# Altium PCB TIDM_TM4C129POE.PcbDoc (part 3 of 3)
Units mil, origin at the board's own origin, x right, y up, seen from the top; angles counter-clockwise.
Board outline 4950 x 3450 mil, 4 copper layers (Component Side, Ground Plane, Power Plane, Solder Side), stack 59.6 mil thick; 159 components, 154 nets, 570 pads, 297 vias.
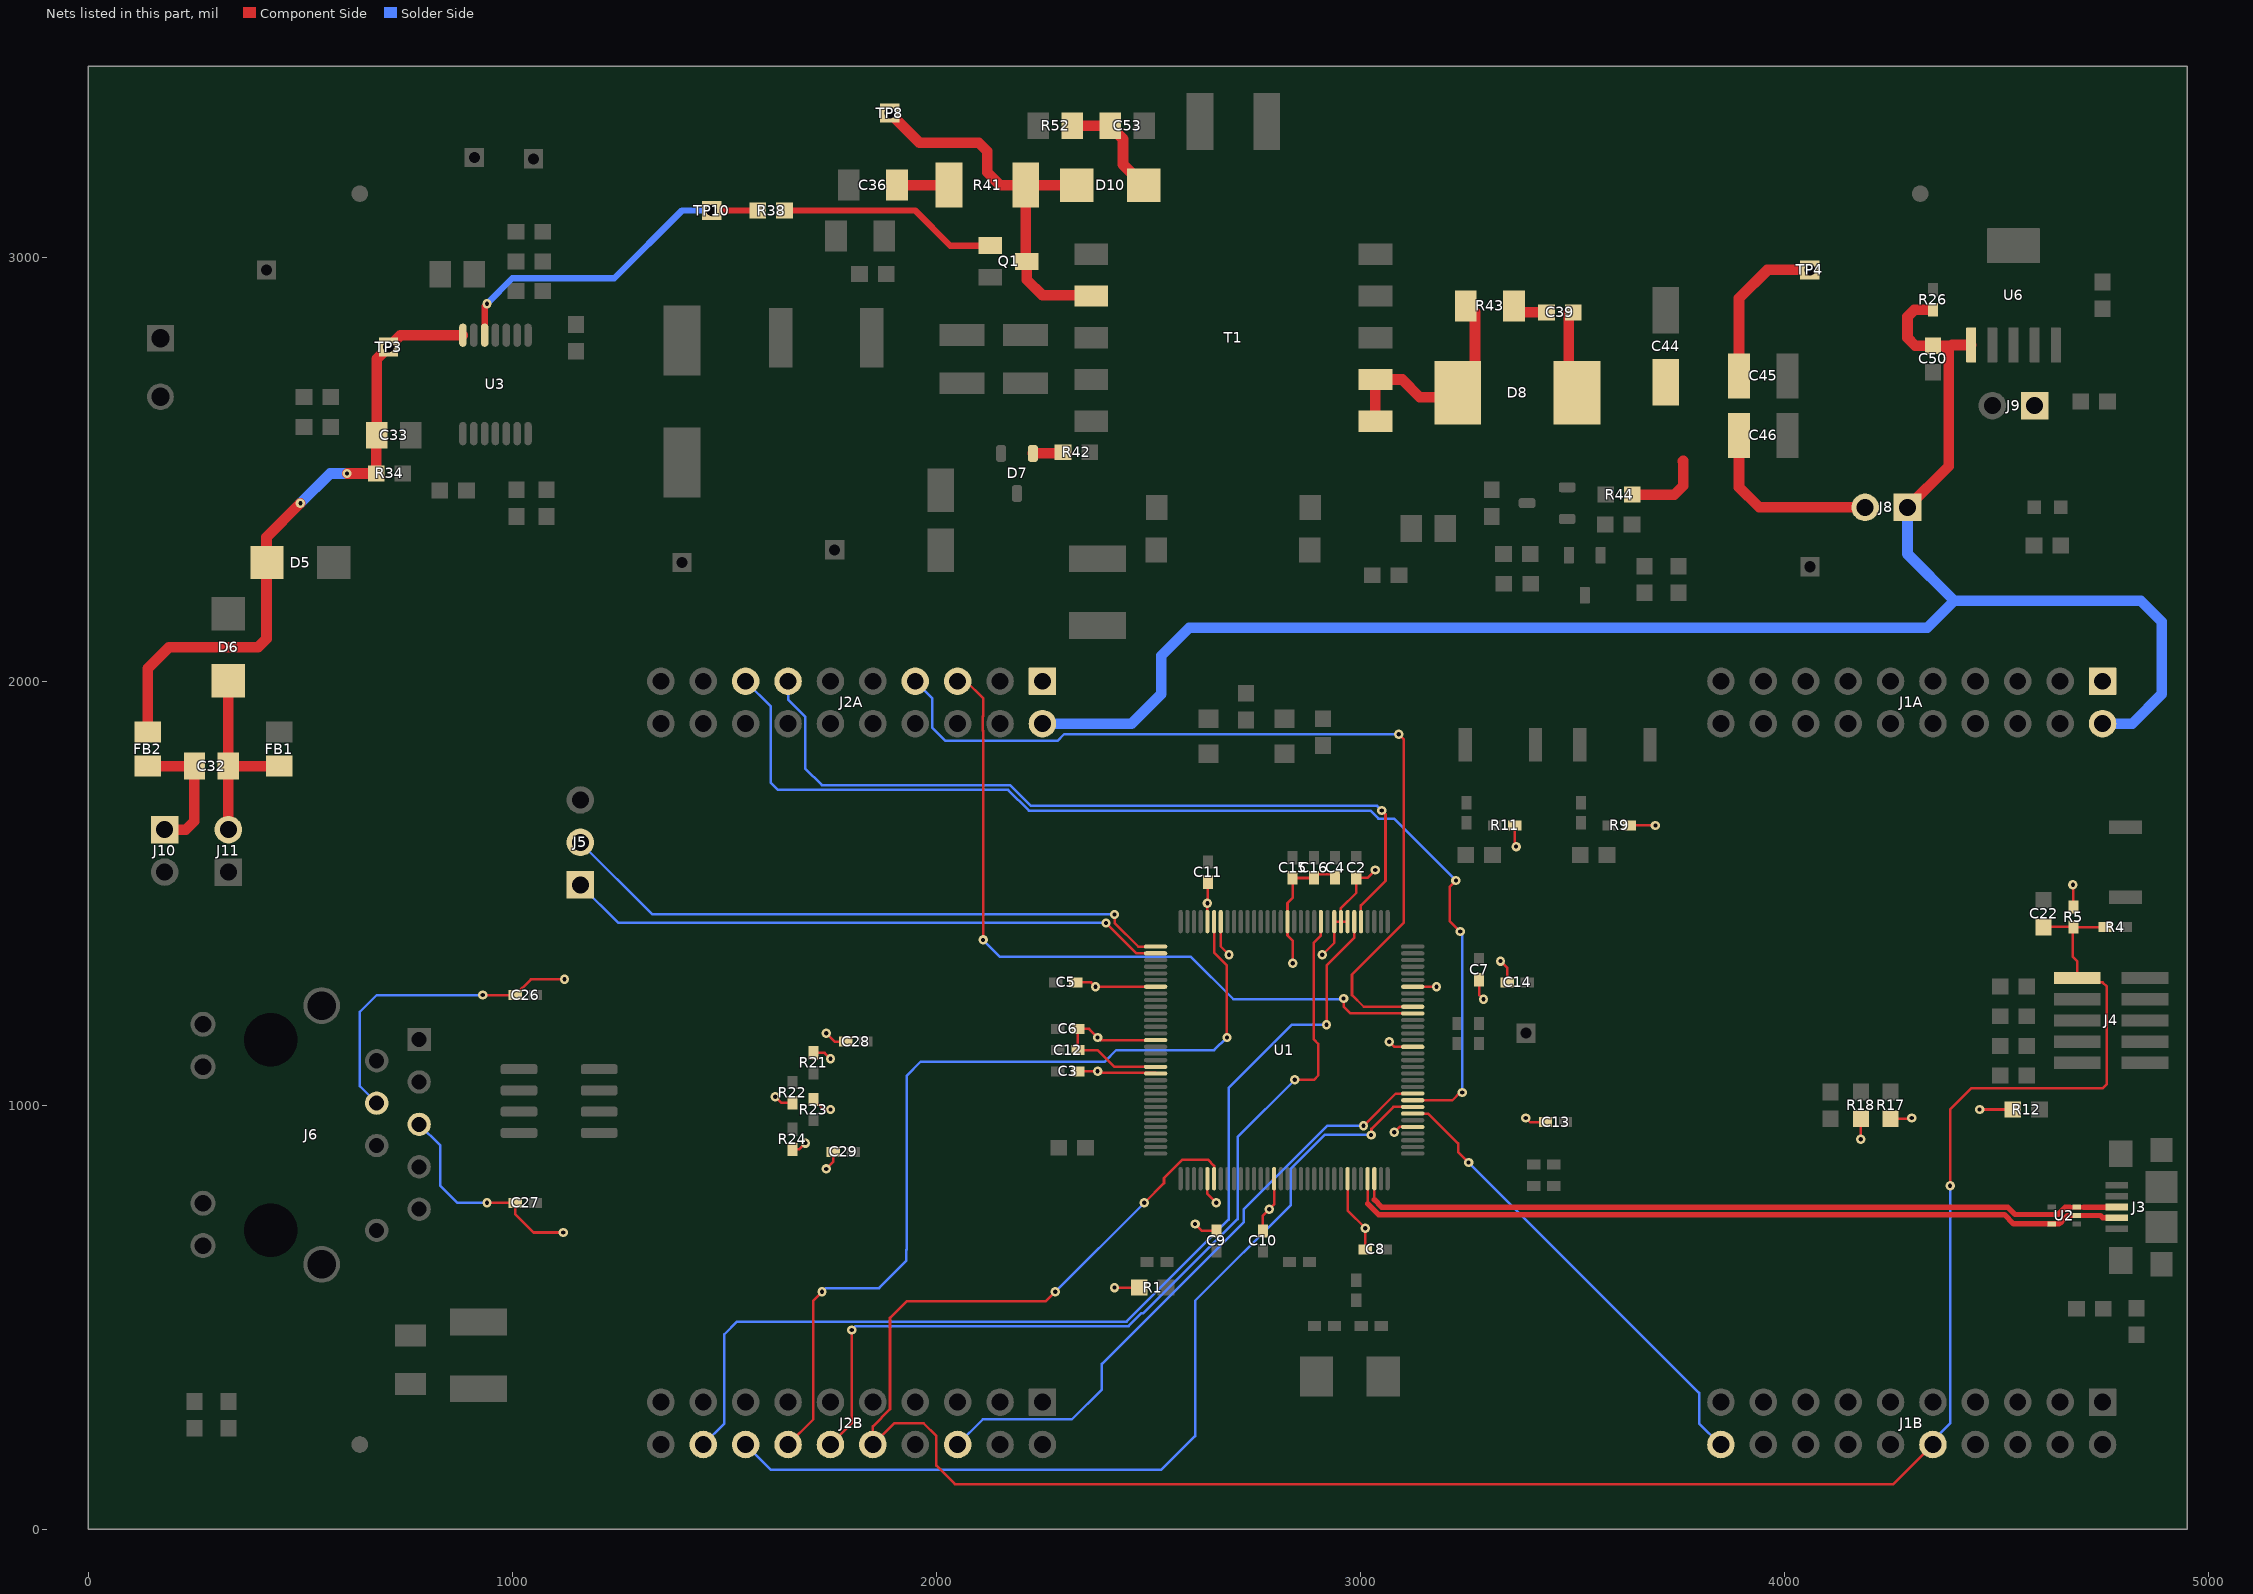
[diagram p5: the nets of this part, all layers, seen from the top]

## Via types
v1: diameter 22, hole 10, Component Side to Solder Side, 297 vias

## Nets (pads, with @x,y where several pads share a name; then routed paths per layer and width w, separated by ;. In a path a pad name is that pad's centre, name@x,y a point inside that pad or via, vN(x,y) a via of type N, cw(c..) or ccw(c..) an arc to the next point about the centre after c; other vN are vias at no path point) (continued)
POE_NET08: D10.2 Q1.3 R41.2 T1.4 TP8.1 | length 933
  Component Side w25: TP8.1@1890,3340 1960,3270 2100,3270 2120,3250 2120,3200 2150,3170 R41.2@2210.55,3170 ; D10.2@2331.26,3170 R41.2@2210.55,3170 ; T1.4@2365,2908.43 2363.43,2910 2250,2910 2213.31,2946.69 Q1.3@2213.31,2990 2210.55,2992.76 R41.2@2210.55,3170
POE_NET09: D7.1 R42.1 | length 72.2
  Component Side w25: D7.1@2227.4,2537.24 2295.75,2537.24 R42.1@2298.5,2540
POE_NET10: C36.1 R41.1 | length 122.4
  Component Side w25: C36.1@1907.09,3170 R41.1@2029.45,3170
POE_NET11: D8.2 R43.1 T1.9 T1.10 | length 526.7
  Component Side w25: T1.10@3035,2613.15 T1.9@3035,2711.57 3098.43,2711.57 3140,2670 3229.19,2670 3270,2710.81 R43.1@3270,2870
POE_NET12: C39.1 C44.1 C45.1 C46.1 D8.1 J8.2 R44.2 TP4.1 | length 1205
  Component Side w25: C39.1@3491.5,2870 3491.5,2699 D8.1@3510.49,2680 ; R44.2@3641.18,2440 3740,2440 3761.18,2461.18 3761.18,2520 3759.68,2518.5 ; C46.1@3892.6,2580 3892.6,2457.4 3940,2410 J8.2@4190,2410 ; C45.1@3892.6,2720 3892.6,2902.91 3959.68,2970 TP4.1@4059.68,2970
POE_NET13: C39.2 R43.2 | length 78.5
  Component Side w25: R43.2@3350,2870 C39.2@3428.5,2870
POE_NET14: C53.2 D10.1 R52.1 | length 262.6
  Component Side w25: R52.1@2320,3310 C53.2@2410,3310 2410,3308.75 2440,3278.75 2440,3218.74 D10.1@2488.74,3170
POE_NET15: C33.2 D5.2 FB2.2 R34.1 TP3.1 U3.7 | length 1516
  Component Side w25: FB2.2@140,1880 140,2030 190,2080 400,2080 420,2100 420,2340 v1(500,2420) ; v1(610,2490) R34.1@678.5,2490 678.5,2578.5 C33.2@680,2580 680,2760 TP3.1@708.07,2788.07 736.14,2816.14 U3.7@882.46,2816.14
  Solder Side w25: v1(500,2420) 570,2490 v1(610,2490)
POE_VN: C32.2 FB2.1 J10.1 | length 318.3
  Component Side w25: FB2.1@140,1800 C32.2@250,1800 250,1670 230,1650 J10.1@180,1650
POE_VP: C32.1 D6.1 FB1.1 J11.2 | length 471.3
  Component Side w25: J11.2@330,1650 C32.1@330,1800 ; D6.1@330,2001.26 C32.1@330,1800 ; FB1.1@450,1800 C32.1@330,1800
PP0: J2A.5 U1.118 | length 1746.1
  Component Side w6: J2A.5@2050,2000 2070,2000 2110,1960 2110,1917.73 2109.52,1917.25 2109.52,1883.23 2110,1882.75 v1(2110,1390) ; v1(2960.22,1252) 2960.22,1233.22 2960,1233 2976.39,1216.61 U1.118@3123.15,1216.61
  Solder Side w6: v1(2110,1390) 2150,1350 2600,1350 2700,1250 2960,1250 2960.22,1250.22 v1(2960.22,1252)
PP1: J2A.7 U1.119 | length 2070.8
  Component Side w6: v1(3090,1875) 3102.44,1862.56 3102.44,1430.59 2980,1308.14 2980,1260 3007.64,1232.36 U1.119@3123.15,1232.36
  Solder Side w6: J2A.7@1950,2000 1990,1960 1990,1917.73 1990.48,1917.25 1990.48,1890 2020.96,1859.52 2285.79,1859.52 2301.27,1875 v1(3090,1875)
PP2: J1B.20 U1.103 | length 1103.8
  Component Side w6: U1.103@3123.15,980.39 3159.44,980.39 3187.68,952.15 3187.87,952.15 3230.1,909.92 3230.1,889.9 v1(3255,865)
  Solder Side w6: v1(3255,865) 3798.42,321.58 3798.42,250 3848.42,200 J1B.20@3850,200
PP3: J2B.16 U1.104 | length 2198
  Component Side w6: v1(3025,930) 3026,930 3026,944.5 3077.64,996.14 U1.104@3123.15,996.14
  Solder Side w6: J2B.16@1550,200 1610,140 2530,140 2610,220 2610,539 2835,764 2835,849.44 2915.56,930 v1(3025,930)
PP4: J2A.15 U1.105 | length 2623.1
  Component Side w6: U1.105@3123.15,1011.89 3216.89,1011.89 3235,1030 v1(3240,1030) ; v1(3225,1530) 3210,1515 3210,1435 v1(3235,1410)
  Solder Side w6: J2A.15@1550,2000 1609.52,1940.48 1609.52,1760.48 1626,1744 2169,1744 2218,1695 3023.13,1695 3042.13,1676 3079,1676 v1(3225,1530) ; v1(3235,1410) 3240,1405 v1(3240,1030) v1@3240,1025
PP5: J2B.6 U1.106 | length 1468.7
  Component Side w6: v1(3007,951.5) 3083.14,1027.64 U1.106@3123.15,1027.64
  Solder Side w6: J2B.6@2050,200 2109.52,259.52 2319.52,259.52 2390,330 2390,390 2725,725 2725,755 2921.5,951.5 v1(3007,951.5)
PQ0: J2A.13 U1.5 | length 1912.5
  Component Side w6: U1.5@3001.1,1433.15 3001.1,1471.1 3059,1529 3059,1686 v1(3050,1695)
  Solder Side w6: J2A.13@1650,2000 1650,1957.25 1690.48,1916.77 1690.48,1794.52 1730,1755 2173.56,1755 2222.56,1706 3039,1706 v1(3050,1695)
PQ1: J2B.18 U1.6 | length 2454.8
  Component Side w6: v1(2920,1190) 2920,1330 2985.35,1395.35 U1.6@2985.35,1433.15
  Solder Side w6: J2B.18@1450,200 1500,250 1500,460 1530,490 2448.35,490 2689,730.65 2689,1040.44 2838.56,1190 v1(2920,1190)
PQ2: J2B.12 U1.11 | length 2126.9
  Component Side w6: J2B.12@1750,200 1800,250 v1(1800,470) ; v1(2845,1060) 2890,1060 2900.36,1070.36 2900.36,1145 2890,1155.36 2890,1383.8 2906.61,1400.42 U1.11@2906.61,1433.15
  Solder Side w6: v1(1800,470) 1809,479 2452.9,479 2483.9,510 2488.19,510 2710,731.81 2710,925 v1(2845,1060)
PQ3: J2B.14 U1.27 | length 2137.5
  Component Side w6: J2B.14@1650,200 1709.52,259.52 1709.52,539.52 v1(1730,560) ; U1.27@2654.65,1433.15 2654.65,1360 2685,1329.65 v1(2685,1160)
  Solder Side w6: v1(1730,560) 1739,569 1864.56,569 1929,633.44 1929,659 1930,660 1930,1070 1963,1103 2397,1103 2424,1130 2655,1130 v1(2685,1160)
RST_N: C22.1 J1B.10 J2B.10 J4.10 R4.1 R5.1 U1.70 | length 5722.5
  Component Side w6: v1(2280,560) 2258,538 1930,538 1890.48,498.48 1890.48,283.23 1850,242.75 J2B.10@1850,200 1900,250 1970,250 2000,220 2000,150 2043.5,106.5 4256.5,106.5 J1B.10@4350,200 ; v1(2490,770) 2536.56,816.56 2536.56,828.44 2580.08,871.97 2640,871.97 2654.65,857.32 U1.70@2654.65,826.85 ; v1(4390.48,810) 4390.48,990.48 4440,1040 4750,1040 4760,1050 4760,1280 4750,1290 J4.10@4681,1290 ; C22.1@4611,1420.5 4681,1420.5 R5.1@4681,1420.38 R5.1@4681,1420 ; J4.10@4689.88,1300 4689.88,1340.12 4680,1350 4680,1419 R5.1@4681,1420 ; R4.1@4756.38,1420 R5.1@4681,1420
  Solder Side w6: v1(2280,560) v1(2490,770) ; J1B.10@4350,200 4350,209.52 4390.48,250 v1(4390.48,810)
TRC_001: Q1.1 R38.2 | length 519.4
  Component Side w15: R38.2@1641.5,3110 1950,3110 2032.6,3027.4 Q1.1@2126.69,3027.4
TRC_002: R38.1 TP10.1 U3.5 | length 805.8
  Component Side w15: U3.5@934.41,2816.14 934.41,2884.41 v1(940,2890) ; TP10.1@1470,3110 R38.1@1578.5,3110
  Solder Side w15: v1(940,2890) 1000,2950 1240,2950 1400,3110 TP10.1@1470,3110
UART0RX: J5.2 U1.33 | length 1470.4
  Component Side w6: v1(2420,1450) 2420,1430 2475.91,1374.09 U1.33@2516.85,1374.09
  Solder Side w6: J5.2@1160,1620 1330,1450 v1(2420,1450)
UART0TX: J5.1 U1.34 | length 1423.8
  Component Side w6: v1(2400,1430) 2471.65,1358.35 U1.34@2516.85,1358.35
  Solder Side w6: J5.1@1160,1520 1250,1430 v1(2400,1430)
USBD_N: J3.2 U1.93 U2.2 U2.5 | length 1855.9
  Component Side w6: 3016.85,767.98 U1.93@3016.85,826.85
  Component Side w12.8: 3016.85,767.98 3042.63,742.2 4518.55,742.2 4540.44,720.31 U2.5@4630.47,720.31 4646.71,720.31 4650.98,724.58 4652.41,724.58 4667.83,740 U2.2@4689.53,740 4745.1,740 4750.69,734.41 J3.2@4783.66,734.41
USBD_P: J3.3 U1.94 U2.3 | length 1822.3
  Component Side w6: 3032.6,777.4 U1.94@3032.6,826.85
  Component Side w10.63: 4673.29,759.68 U2.3@4689.53,759.68 4705.77,759.68
  Component Side w12.8: 3032.6,777.4 3050,760 4525.93,760 4543.55,742.38 4645.04,742.38 4662.34,759.68 4673.29,759.68 ; 4705.77,759.68 4750.37,759.68 4750.69,760 J3.3@4783.66,760
VCC_3P3: C2.1 C3.1 C4.1 C5.1 C6.1 C7.1 C8.1 C9.1 C10.1 C11.1 C12.1 C13.1 C14.1 C15.1 C16.1 C26.1 C27.1 C28.1 C29.1 J1A.1 J2A.1 J6.4 J6.5 J9.1 R1.1 R5.2 R9.2 R11.2 R12.1 R17.2 R18.2 R21.2 R22.2 R23.2 R24.2 U1.7 U1.8 U1.9 U1.16 U1.26 U1.28 U1.39 U1.47 U1.51 U1.52 U1.69 U1.79 U1.90 U1.101 U1.113 U1.122 | length 4344.2
  Component Side w6: v1(930,1260) C26.1@1006.38,1260 1043.37,1296.99 v1(1123,1296.99) ; v1(940,770) C27.1@1006.38,770 1006.38,743.62 1050,700 v1(1120,700) ; v1(1620,1020) 1633.62,1006.38 R22.2@1660,1006.38 ; R24.2@1660,896.38 1676.84,896.38 v1(1691.21,910.75) ; R23.2@1710,1013.62 1733.62,990 v1(1750,990) ; R21.2@1710,1123.62 1736.38,1123.62 v1(1750,1110) ; v1(1740,850) 1756.38,866.38 C29.1@1756.38,890 ; v1(1740,1170) 1760,1150 C28.1@1786.38,1150 ; C5.1@2328.62,1290 2364.61,1290 v1(2375,1279.61) U1.39@2516.85,1279.61 ; C3.1@2333.62,1080 v1(2380,1080) 2383.82,1076.18 2516.85,1076.18 U1.52@2516.85,1074.88 ; v1(2420,570) R1.1@2478.5,570 ; U1.51@2516.85,1090.63 2419.37,1090.63 2380,1130 C12.1@2333.62,1130 C6.1@2333.62,1180 2360,1180 v1(2380,1160) 2386.38,1153.62 U1.47@2516.85,1153.62 ; v1(2610,720) 2626.38,703.62 C9.1@2660,703.62 C9.1@2660,703 ; U1.69@2638.9,826.85 2638.9,791.1 v1(2660,770) ; U1.28@2638.9,1433.15 v1@2638.9,1475.9 ; v1(2638.9,1476.71) v1@2638.9,1475.9 ; C11.1@2640,1526.38 2640,1477 v1@2638.9,1475.9 ; U1.26@2670.39,1433.15 2670.39,1374.61 v1(2690,1355) ; C10.1@2770,703.62 2770,740 v1(2785,755) 2796.38,766.38 U1.79@2796.38,826.85 U1.79@2793.55,824.02 ; v1(2840,1335) 2840,1388.29 2827.87,1400.42 U1.16@2827.87,1433.15 2827.87,1477 2828,1477 2840,1489 C15.1@2840,1536 ; C15.1@2840,1536.38 C15.1@2840,1536 ; v1(2910,1355) 2938.11,1383.11 U1.9@2938.11,1433.15 U1.8@2953.86,1433.15 ; C4.1@2940,1536.38 2940,1544.78 2890,1544.78 C16.1@2890,1536.38 2890,1536 C15.1@2840,1536 ; U1.90@2969.61,826.85 2969.61,751.77 v1(3011.38,710) C8.1@3011.38,660 ; U1.7@2969.61,1433.15 U1.8@2953.86,1433.15 ; v1(3035,1555) 3016.38,1536.38 C2.1@2990,1536.38 2990,1500.86 2953.86,1464.72 U1.8@2953.86,1433.15 ; v1(3068.03,1150) 3080.16,1137.87 U1.113@3123.15,1137.87 ; v1(3079.59,936.4) 3092.09,948.9 U1.101@3123.15,948.9 ; U1.122@3123.15,1279.61 v1(3179.21,1279.61) ; C7.1@3280,1296.38 3280,1260 v1(3290,1250) ; v1(3330,1340) 3346.38,1323.62 C14.1@3346.38,1290 ; R11.2@3363.62,1660 3363.62,1613.38 v1(3367,1610) ; v1(3390,970) 3400,960 C13.1@3436.38,960 ; R9.2@3633.62,1660 v1(3695.5,1660) ; v1(4180,920) R18.2@4180,968.5 R18.2@4180,969 ; R17.2@4250,968.5 4298.5,968.5 v1(4300,970) ; v1(4460,990) R12.1@4538.5,990 ; v1(4680,1520) 4681,1519 R5.2@4681,1467.62 R5.2@4681,1461
  Solder Side w6: J6.4@680,1005 640,1045 640,1220 680,1260 v1(930,1260) ; J6.5@780,955 830,905 830,810 870,770 v1(940,770)
VCC_5P0: C50.1 J1A.2 J2A.2 J8.1 R26.1 U6.1 | length 4140.2
  Component Side w25: J8.1@4290,2410 4387,2507 4387,2778.5 4374,2791.5 ; R26.1@4350,2876.38 4306.38,2876.38 4290,2860 4290,2810 4308.5,2791.5 C50.1@4350,2791.5 4374,2791.5 ; U6.1@4440,2792.87 4395.38,2792.87 4394,2791.5 4374,2791.5
  Solder Side w25: J2A.2@2250,1900 2460,1900 2530,1970 2530,2060 2596.5,2126.5 4336.5,2126.5 4400,2190 ; J8.1@4290,2410 4290,2300 4400,2190 ; J1A.2@4750,1900 4820,1900 4890,1970 4890,2140 4840,2190 4400,2190
pads on no net: D7.2 FID1.1 FID2.1 FID3.1 J3.1 J3.4 J4.7 J6.MH1 J6.MH2 T1.5 T1.6 U1.65 U1.67 U1.72 U1.76 U1.77 U1.102 U2.1

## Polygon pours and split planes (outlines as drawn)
GNDX on Ground Plane (split plane): 2649.92,2250.08 1030,2250.08 1024.39,2249.76 1018.86,2248.82 1013.46,2247.27 1008.27,2245.12 1003.36,2242.4 998.78,2239.15 994.59,2235.41 990.85,2231.22 987.6,2226.64 984.88,2221.73 982.73,2216.54 981.18,2211.14 980.24,2205.61 979.92,2200 979.92,1865.08 50.08,1865.08 50.08,3399.92 2649.92,3399.92
E_SHIELD on Ground Plane (split plane): 987.6,1813.36 990.85,1808.78 994.59,1804.59 998.78,1800.85 1003.36,1797.6 1004.92,1796.73 1004.92,1170 1005.23,1166.08 1006.15,1162.25 1007.66,1158.62 1009.71,1155.26 1012.27,1152.27 1015.26,1149.71 1018.62,1147.66 1022.25,1146.15 1026.08,1145.23 1030,1144.92 1304.92,1144.92 1304.92,875.08 1030,875.08 1026.08,874.77 1022.25,873.85 1018.62,872.34 1015.26,870.29 1012.27,867.73 1009.71,864.74 1007.66,861.38 1006.15,857.75 1005.23,853.92 1004.92,850 1004.92,435.08 50.08,435.08 50.08,1814.92 986.73,1814.92
GND on Ground Plane (split plane): 4899.92,50.08 50.08,50.08 50.08,384.92 1030,384.92 1033.92,385.23 1037.75,386.15 1041.38,387.66 1044.74,389.71 1047.73,392.27 1050.29,395.26 1052.34,398.62 1053.85,402.25 1054.77,406.08 1055.08,410 1055.08,824.92 1330,824.92 1333.92,825.23 1337.75,826.15 1341.38,827.66 1344.74,829.71 1347.73,832.27 1350.29,835.26 1352.34,838.62 1353.85,842.25 1354.77,846.08 1355.08,850 1355.08,1170 1354.77,1173.92 1353.85,1177.75 1352.34,1181.38 1350.29,1184.74 1347.73,1187.73 1344.74,1190.29 1341.38,1192.34 1337.75,1193.85 1333.92,1194.77 1330,1195.08 1055.08,1195.08 1055.08,1796.73 1056.64,1797.6 1061.22,1800.85 1065.41,1804.59 1069.15,1808.78 1072.4,1813.36 1075.12,1818.27 1077.27,1823.46 1078.82,1828.86 1079.76,1834.39 1080.08,1840 1080.08,2149.92 2700,2149.92 2705.61,2150.24 2711.14,2151.18 2716.54,2152.73 2721.73,2154.88 2726.64,2157.6 2731.22,2160.85 2735.41,2164.59 2739.15,2168.78 2742.4,2173.36 2745.12,2178.27 2747.27,2183.46 2748.82,2188.86 2749.76,2194.39 2750.08,2200 2750.08,3399.92 4899.92,3399.92
VCC_3P3 on Power Plane (split plane): 4929.9,20.1 20.1,20.1 20.1,394.93 1030,394.93 1032.94,395.22 1035.77,396.07 1038.37,397.47 1040.66,399.34 1042.53,401.63 1043.93,404.23 1044.78,407.06 1045.07,410 1045.07,834.93 1330,834.93 1332.94,835.22 1335.77,836.07 1338.37,837.47 1340.66,839.34 1342.53,841.63 1343.93,844.23 1344.78,847.06 1345.07,850 1345.07,1170 1344.78,1172.94 1343.93,1175.77 1342.53,1178.37 1340.66,1180.66 1338.37,1182.53 1335.77,1183.93 1332.94,1184.78 1330,1185.07 1045.07,1185.07 1045.07,1400 1045.07,2184.93 2700,2184.93 2702.94,2185.22 2705.77,2186.07 2708.37,2187.47 2710.66,2189.34 2712.53,2191.63 2713.93,2194.23 2714.78,2197.06 2715.07,2200 2715.07,3429.9 4929.9,3429.9

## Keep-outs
Keep-Out Layer:
  lines w10: -5,0 -5,3450 ; 0,-5 4950,-5 ; 0,3455 4950,3455 ; 4955,0 4955,3450
  text ".Layer_Name" at 577,-853.49 h60

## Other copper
Component Side:
  rectangle net POE_NET11: 3210,2760 3300,2931.26
  rectangle net POE_NET12: 3470,2780 3531.02,2905
  rectangle net POE_NET12: 3729.68,2490 3949.68,2630
  rectangle net POE_NET12: 3419.68,2570 3949.68,2800
  rectangle net POE_NET08: 2170,2870 2310,3250
  rectangle net POE_NET08: 2170,2870 2420,2960
  rectangle net POE_NET08: 2260,3101.1 2410,3250
  rectangle net POE_NET05: 1810,2760 2420,2860
  rectangle net POE_NET05: 1797.09,2720 1950,2910.39
  rectangle net POE_NET11: 2990,2570 3300,2760
  rectangle net GND: 4400,2955 4679.76,3160
  text ".Layer_Name" at 577,-853.49 h60
Solder Side:
  text ".Layer_Name" at 577,-853.49 h60
Ground Plane (plane layer: these items are gaps in the copper):
  lines w10: 0,2920 0,0 1130,0 1140,10
  lines w50: 0,410 1030,410 1030,850 1330,850 1330,1170 1030,1170 1030,1840 0,1840
  lines w100: 1030,1840 1030,2200 2700,2200 2700,3450
  text ".Layer_Name" at 577,-853.49 h60
Power Plane (plane layer: these items are gaps in the copper):
  rectangle: 0,2200 2690,3450
  rectangle: 0,410 1030,2200
  rectangle: 1030,850 1330,1170
  lines w10: 0,3450 2700,3450 4950,3450 4950,0 0,0 0,3455
  lines w30: 0,410 1030,410 1030,850 1330,850 1330,1170 1030,1170 1030,1400 1030,2200 2700,2200 2700,3450
  text ".Layer_Name" at 577,-853.49 h60

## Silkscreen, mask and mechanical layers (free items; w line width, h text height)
Top Overlay:
  lines w10: 3455,1150 3435,1170 ; 3490,1170 3435,1170 ; 3940,2265 4010,2265 ; 3955,2250 3995,2250 ; 3975,2225 3975,2235 ; 3975,2330 3975,2280 3930,2280 4020,2280 ; 4260,2510 4290,2480 ; 4290,2550 4290,2480 ; 4319.01,2509.08 4319.01,2509.01 4290,2480 ; 4575,2545 4600,2570 ; 4625,2545 4600,2570 ; 4650,2500 4600,2500 4600,2535 4600,2570 ; 3435,1170 3455,1190 3435,1170
  text "TIDM-TM4C129POE A0" at 3170,3300 h60
  text "5P0" at 4270,2675 h40 r270
  text "3P3" at 4665,2480 h40
  text "3P3" at 2230,2245 h40 r270
  text "PN4" at 1320,2170 h40 r270
  text "PN5" at 1430,2170 h40 r270
  text "PP4" at 1520,2170 h40 r270
  text "PQ0" at 1620,2170 h40 r270
  text "PD5" at 1720,2170 h40 r270
  text "PD4" at 1820,2170 h40 r270
  text "PP1" at 1920,2170 h40 r270
  text "PP0" at 2020,2170 h40 r270
  text "PD2" at 2120,2170 h40 r270
  text "PB3" at 3830,2170 h40 r270
  text "PB2" at 3930,2170 h40 r270
  text "PC7" at 4030,2170 h40 r270
  text "PD3" at 4120,2170 h40 r270
  text "PE5" at 4220,2170 h40 r270
  text "PC6" at 4330,2170 h40 r270
  text "PC5" at 4430,2170 h40 r270
  text "PC4" at 4530,2170 h40 r270
  text "PE4" at 4630,2170 h40 r270
  text "3P3" at 4730,2170 h40 r270
  text "(PJ1)" at 2780,2050 h40
  text "(PJ0)" at 2500,1980 h40 r270
  text "(PN0)" at 3320,1930 h40
  text "PA5" at 1330,1830 h40 r270
  text "PA4" at 1430,1830 h40 r270
  text "PK3" at 1530,1830 h40 r270
  text "PK2" at 1630,1830 h40 r270
  text "PK1" at 1730,1830 h40 r270
  text "PK0" at 1830,1830 h40 r270
  text "PB5" at 1930,1830 h40 r270
  text "PB4" at 2030,1830 h40 r270
  text "GND" at 2130,1830 h40 r270
  text "5P0" at 2230,1830 h40 r270
  text "PM5" at 3830,1830 h40 r270
  text "PM4" at 3930,1830 h40 r270
  text "PD6" at 4030,1830 h40 r270
  text "PD7" at 4120,1830 h40 r270
  text "PE3" at 4230,1830 h40 r270
  text "PE2" at 4330,1830 h40 r270
  text "PE1" at 4430,1830 h40 r270
  text "PE0" at 4530,1830 h40 r270
  text "GND" at 4630,1830 h40 r270
  text "5P0" at 4730,1830 h40 r270
  text "GND" at 1110,1790 h40
  text "(PN1)" at 3570,1730 h40
  text "RST" at 4630,1640 h40
  text "U0RX" at 1240,1600 h40
  text "U0TX" at 1240,1500 h40
  text "1P2" at 3510,1155 h40
  text "." at 4810,1030 h40
  text "PK7" at 1330,480 h40 r270
  text "PK6" at 1430,480 h40 r270
  text "PH1" at 1530,480 h40 r270
  text "PH0" at 1630,480 h40 r270
  text "PA3" at 1720,480 h40 r270
  text "PA2" at 1830,479 h40 r270
  text "PA6" at 1930,479 h40 r270
  text "PK5" at 2020,479 h40 r270
  text "PK4" at 2120,479 h40 r270
  text "PG1" at 2230,479 h40 r270
  text "PL3" at 3820,470 h40 r270
  text "PL2" at 3920,470 h40 r270
  text "PL1" at 4020,470 h40 r270
  text "PL0" at 4110,470 h40 r270
  text "PL5" at 4220,470 h40 r270
  text "PL4" at 4320,470 h40 r270
  text "PG0" at 4420,470 h40 r270
  text "PF3" at 4520,470 h40 r270
  text "PF2" at 4620,470 h40 r270
  text "PF1" at 4730,470 h40 r270
  text "PP2" at 3830,137.5 h40 r270
  text "PN3" at 3930,137.5 h40 r270
  text "PM0" at 1330,135 h40 r270
  text "PQ1" at 1440,135 h40 r270
  text "PP3" at 1530,135 h40 r270
  text "PQ3" at 1630,135 h40 r270
  text "PQ2" at 1730,135 h40 r270
  text "RST" at 1830,135 h40 r270
  text "PA7" at 1925,135 h40 r270
  text "PP5" at 2030,135 h40 r270
  text "PM7" at 2130,135 h40 r270
  text "GND" at 2240,135 h40 r270
  text "PN2" at 4030,135 h40 r270
  text "PD0" at 4130,135 h40 r270
  text "PD1" at 4230,135 h40 r270
  text "RST" at 4330,135 h40 r270
  text "PH3" at 4430,135 h40 r270
  text "PH2" at 4530,135 h40 r270
  text "PM3" at 4630,135 h40 r270
  text "GND" at 4740,135 h40 r270
  text ".Layer_Name" at 577,-853.49 h60
Bottom Overlay:
  text "AAA" at 4290,1350 h40
  text ".Layer_Name" at 577,-853.49 h60
Top Paste:
  text ".Layer_Name" at 577,-853.49 h60
Bottom Paste:
  text ".Layer_Name" at 577,-853.49 h60
Top Solder:
  text ".Layer_Name" at 577,-853.49 h60
  text ".Layer_Name" at 577,-853.49 h60
Bottom Solder:
  text ".Layer_Name" at 577,-853.49 h60
Drill Guide:
  text ".Layer_Name" at 577,-853.49 h60
Mechanical 1:
  the board outline again, w10
Mechanical 2:
  rectangle: 125,-400 500,-275
  rectangle: 0,-275 125,-150
  rectangle: 125,-395 500,-270
  lines w7: 0,-395 1000,-395 ; 0,-275 1000,-275 ; 0,-270 1000,-270 ; 125,-400 125,-150 ; 250,-400 250,-150 ; 500,-400 500,-150 ; 750,-400 750,-150 ; 0,-400 1000,-400 1000,-150 0,-150 0,-400
  text ".Layer_Name" at 577,-853.49 h60
Mechanical 3:
  text ".Layer_Name" at 577,-853.49 h60
Mechanical 4:
  text ".Layer_Name" at 577,-853.49 h60
Mechanical 5:
  lines w10: -292,-1133.5 6310,-1133.5 6309,-524 ; -292,-930.17 6308,-930.17 ; -292,-726.83 6310,-726.83 ; -291.5,-1133.5 -291.5,-523.5 6310,-523.5 ; 2160,-1128.5 2160,-518.5 ; 3440,-721.83 3440,-518.5 ; 4280,-721.83 4280,-518.5 ; 4930,-1130 4930,-927.17
  text "COMPONENTS MARKED 'DNP' SHOULD NOT BE POPULATED." at 1153.5,-313.5 h60
  text "ASSEMBLY VARIANT:" at 1153,-429 h60
  text ".VariantName" at 2189,-429 h60
  text "PCB VIEWED FROM TOP SIDE" at -228.5,-650.67 h60
  text "BOARD #:" at 2248,-650.67 h60
  text ".PRJ_Number" at 2793.5,-650.67 h60
  text "REV:" at 3638,-650.67 h60
  text ".PCB_Rev" at 3929.5,-650.67 h60
  text "SVN REV:" at 4476,-650.67 h60
  text ".VersionControl_RevNumber" at 4982,-650.67 h60
  text "LAYER NAME =" at -228.5,-853.49 h60
  text "TID #:" at 2248,-854 h60
  text ".TID" at 2793.5,-854 h60
  text "PLOT NAME =" at -228.5,-1059.34 h60
  text ".plot_File_Name" at 492,-1059.34 h60
  text "GENERATED    :" at 2250,-1059.34 h60
  text ".Print_Date" at 3119.5,-1059.34 h60
  text ".Print_Time" at 3848.5,-1059.34 h60
  text "TEXAS INSTRUMENTS" at 5113,-1059.34 h60
Mechanical 6:
  lines w10: -292.5,-1134 2304.5,-1134 ; -292.5,-727.33 6309.5,-727.33 ; -292.5,-524 6309,-524 ; -290.5,-930.67 6309.5,-930.67 ; 1737.5,-722.33 1737.5,-519 ; 2577.5,-722.33 2577.5,-519 ; 6308,-1129 6308,-519 ; 6308.5,-1129 6308.5,-519
  text "COMPONENTS MARKED 'DNP' SHOULD NOT BE POPULATED." at 6102,-313 h60
  text ".VariantName" at 5058,-429 h60
  text "ASSEMBLY VARIANT:" at 6097,-429 h60
  text ".VersionControl_RevNumber" at 1035.5,-651.17 h60
  text "SVN REV:" at 1541.5,-651.17 h60
  text ".PCB_Rev" at 2088,-651.17 h60
  text "REV:" at 2379.5,-651.17 h60
  text ".PRJ_Number" at 3224,-651.17 h60
  text "BOARD #:" at 3769.5,-651.17 h60
  text "PCB VIEWED FROM BOTTOM SIDE" at 6246,-651.17 h60
  text ".TID" at 3224,-854.5 h60
  text "TID #:" at 3769.5,-854.5 h60
  text "TEXAS INSTRUMENTS" at 904.5,-1059.84 h60
  text ".Print_Time" at 2169,-1059.84 h60
  text ".Print_Date" at 2898,-1059.84 h60
  text "GENERATED    :" at 3767.5,-1059.84 h60
  text "PLOT NAME =" at 6246,-1059.84 h60
Mechanical 9:
  drawing of 54 lines, arcs and shapes, not listed
  text "1" at 739.84,8036.5 h70
  text "2" at 3235.5,8036.5 h70
  text "3" at 5724.84,8036.5 h70
  text "4" at 8231.51,8036.5 h70
  text "5" at 10730.5,8036.5 h70
  text "6" at 13235.5,8036.5 h70
  text "A" at -416.5,6893.5 h70
  text "A" at 14383.5,6893.5 h70
  text "B" at -416.5,4513.5 h70
  text "B" at 14383.5,4513.5 h70
  text "C" at -416.5,2138.5 h70
  text "C" at 14383.5,2138.5 h70
  text "PROJECT TITLE:" at 11343.5,277.5 h45
  text ".PRJ_Title" at 11393.5,144.17 h70
  text "DESIGNED FOR:" at 11343.5,-23.5 h45
  text ".PRJ_Customer" at 11393.5,-163.5 h70
  text "D" at -416.5,-231.5 h70
  text "D" at 14383.5,-231.5 h70
  text "FILE NAME:" at 11343.5,-323.5 h45
  text ".PCB_File_Name_No_Path" at 11393.5,-443.5 h70
  text "Texas Instruments (TI) and/or its licensors do not warrant the accuracy or completeness of this specification" at 6374,-605.34 h45
  text "ENGINEER:" at 11343.5,-613.5 h45
  text "LAYOUT BY:" at 12848.5,-613.5 h45
  text "or any information contained therein. TI and/or its licensors do not warrant that this design will meet" at 6329.01,-718 h45
  text ".PRJ_Engineer" at 11393.5,-768.49 h70
  text ".PCB_Layout" at 12899,-768.49 h70
  text "the specifications, will be suitable for your application or fit for any particular purpose, or will operate in" at 6329.01,-830.67 h45
  text "ALTIUM DESIGNER VERSION:" at 12848.5,-923.5 h45
  text "an implementation. TI and/or its licensors do not warrant that the design is production worthy. You should" at 6329.01,-943.33 h45
  text "completely validate and test your design implementation to confirm the system functionality for your application." at 6374,-1056 h45
  text ".print_Scale" at 11393.5,-1056.83 h70
  text ".Application_BuildNumber" at 12899,-1056.83 h70
  text "4" at 8231.51,-1263.5 h70
  text "5" at 10730.5,-1263.5 h70
  text "6" at 13235.5,-1263.5 h70
Mechanical 10:
  drawing of 173 lines, arcs and shapes, not listed
  text "DESIGN INFORMATION" at 12377.02,6201 h60
  text "MIN. TRACK WIDTH:" at 11732.46,6021 h60
  text "8" at 12828.7,6021 h60
  text "MIL" at 12983.46,6021 h60
  text "MIN. CLEARANCE:" at 11732.46,5889 h60
  text "0.2" at 12768.7,5889 h60
  text "mm" at 12983.46,5889 h60
  text "MIN. VIA PAD SIZE:" at 11732.46,5757 h60
  text "24" at 12798.71,5757 h60
  text "MIL" at 12983.46,5757 h60
  text "0.05mm (2MIL)" at 12427.46,5615.29 h60
  text "MINIMUM ANNULAR RING" at 11403.23,5611 h60
  text "EXTERNAL" at 13135.46,5611 h60
  text "PER" at 11603.23,5493 h60
  text "IPC-D-275 CLASS 2 LEVEL C" at 11823.23,5493 h60
  text "MIL, HOLES" at 13311.46,5380.71 h60
  text "+/-" at 12919,5380 h60
  text "+/-" at 13773,5380 h60
  text "REGISTRATION TOLERANCES:" at 11403.23,5375 h60
  text "METAL" at 12603,5375 h60
  text "5" at 13179.2,5375 h60
  text "3" at 14012.2,5375 h60
  text "MIL" at 14128.46,5375 h60
  text "+/-" at 13773,5262 h60
  text "HOLE SIZE TOLERANCE (UNLESS OTHERWISE SPECIFIED):" at 11403.23,5257 h60
  text "3" at 14012.2,5257 h60
  text "MIL" at 14128.46,5257 h60
  text "MATERIAL:" at 11328.46,5047.54 h60
  text "FR-4 High Tg" at 12314.9,4907.21 h60
  text "FR-408" at 11749.46,4898.64 h60
  text "OTHER" at 13237.46,4898.64 h60
  text "X" at 12160,4895 h60
  text "62 MIL (1.6mm) +/-10%" at 12069.56,4735.92 h60
  text "THICKNESS:" at 11403.23,4731.64 h60
  text "X" at 11941.4,4731.64 h60
  text "OTHER" at 13354.46,4731.64 h60
  text "TOLERANCE:" at 11403.23,4573.64 h60
  text "X" at 12242.53,4573.64 h60
  text "ANSI IPC-6012 TYPE 3 CLASS 2" at 12429.48,4573.64 h60
  text "OTHER +/-" at 12429.46,4417.64 h60
  text "BOW & TWIST:" at 11403.23,4260.64 h60
  text "X" at 12242.53,4260.64 h60
  text "ANSI IPC-6012 TYPE 3 CLASS 2" at 12429.48,4260.64 h60
  text "OTHER +/-" at 12429.46,4102.13 h60
  text "DRILLING:" at 11328.46,3963.64 h60
  text "REFERENCE:" at 11403.23,3846.64 h60
  text "X" at 12051.46,3846.64 h60
  text "AS SHOWN" at 12238.46,3846.64 h60
  text "X" at 12952.46,3846.64 h60
  text "NC_DRILL FILES" at 13089.46,3846.64 h60
  text "PTH MIN COPPER THICKNESS:" at 11403.23,3688.64 h60
  text "X" at 12753.46,3688.64 h60
  text "1MIL" at 12890.46,3688.64 h60
  text "OTHER" at 13387.46,3688.64 h60
  text "BOARD FINISH:" at 11328.46,3529.64 h60
  text "SILKSCREEN:" at 11483.68,3411.64 h60
  text "X" at 12432.46,3411.64 h60
  text "TOP" at 12558.46,3411.64 h60
  text "X" at 12942.46,3411.64 h60
  text "BOTTOM" at 13069.46,3411.64 h60
  text "SILKSCREEN COLOR:" at 11483.68,3244.64 h60
  text "X" at 12431.42,3244.64 h60
  text "WHITE" at 12558.46,3244.64 h60
  text "OTHER" at 13069.46,3244.64 h60
  text "X" at 12562.42,3085.44 h60
  text "GREEN" at 12689.46,3085.44 h60
  text "OTHER" at 13307.46,3085.44 h60
  text "SOLDER RESIST COLOR:" at 11483.68,3074.64 h60
  text "X" at 12562.42,2915.44 h60
  text "MATTE" at 12689.46,2915.44 h60
  text "SEMI-GLOSS" at 13307,2914.8 h60
  text "IMMERSION GOLD (ENIG)" at 12389.46,2726.92 h60
  text "ENEPIG" at 13727,2723.64 h60
  text "SURFACE FINISH:" at 11328.46,2722.64 h60
  text "X" at 12202.51,2722.64 h60
  text "IMM. TIN/SILVER OR EQUIV" at 11658,2565.64 h60
  text "OTHER" at 13089.46,2565.64 h60
  text "ARRAY/PANEL:" at 11328.46,2386.64 h60
  text "CUT AND TRIM PER M1 BOARD OUTLINE" at 12389.46,2382.35 h60
  text "N.C. ROUTE" at 12389.46,2230.64 h60
  text "X" at 13068.46,2230.64 h60
  text "V. SCORE" at 13255.46,2230.64 h60
  text "CERTIFICATION:" at 11328.46,2093.64 h60
  text "MATERIALS AND WORKMANSHIP FOR ALL PCBS" at 12053.46,2093.64 h60
  text "TO MEET OR EXCEED THE REQUIREMENTS OF:" at 12053.46,1995.64 h60
  text "X" at 11679.96,1859.13 h60
  text "ANSI IPC-A-600F CLASS ->" at 11818.96,1859.13 h60
  text "X" at 13458.02,1859.13 h60
  text "2" at 13576.96,1859.14 h60
  text "1" at 13261.96,1857.64 h60
  text "3" at 13930.96,1857.64 h60
  text "X" at 12494.02,1699.64 h60
  text "RoHS" at 12630.96,1699.64 h60
  text "OTHER" at 13275.36,1699.64 h60
  text "PER ORDER" at 13672.42,1699.64 h60
  text "ALL BOARDS MUST MEET OR EXCEED UL94-V0 REQUIREMENTS." at 11356,1534 h60
  text "PCB MUST BEAR THE UL94V-0 UL REGISTERED MATERIAL ID NUMBER" at 11356,1414 h60
  text "ADDITIONAL REQUIREMENTS:" at 11328.46,1240.64 h60
  text "MICROSECTION:" at 11403.23,1125.64 h60
  text "YES" at 12308.96,1125.64 h60
  text "REQUIRED" at 13170.46,969.49 h60
  text "BARE BOARD ELEC. TEST:" at 11403.23,966.64 h60
  text "NONE" at 12708.96,966.64 h60
  text "X" at 13043.46,966.64 h60
  text "PER ORDER" at 13762.46,966.64 h60
  text ".Layer_Name" at 577,-853.49 h60
Mechanical 11:
  lines w10: -292,-1133.5 3713,-1133.5 ; -292,-930.17 6308,-930.17 ; -292,-726.83 6310,-726.83 ; -291.5,-523.5 6310,-523.5 ; 2160,-1128.5 2160,-518.5 ; 3440,-721.83 3440,-518.5 ; 4280,-721.83 4280,-518.5 ; 6309,-1128.5 6309,-518.5
  text "ALL ARTWORK VIEWED FROM TOP SIDE" at -228.5,-650.67 h60
  text "BOARD #:" at 2248,-650.67 h60
  text ".PRJ_Number" at 2793.5,-650.67 h60
  text "REV:" at 3638,-650.67 h60
  text ".PCB_Rev" at 3929.5,-650.67 h60
  text "SVN REV:" at 4476,-650.67 h60
  text ".VersionControl_RevNumber" at 4982,-650.67 h60
  text "TID #:" at 2248,-854 h60
  text ".TID" at 2793.5,-854 h60
  text "PLOT NAME =" at -228.5,-1059.34 h60
  text "GENERATED    :" at 2250,-1059.34 h60
  text ".Print_Date" at 3119.5,-1059.34 h60
  text ".Print_Time" at 3848.5,-1059.34 h60
  text "TEXAS INSTRUMENTS" at 5113,-1059.34 h60
Mechanical 12:
  drawing of 191 lines, arcs and shapes, not listed
  text "Layer" at 9790.58,7830 h60
  text "Name" at 10200.49,7830 h60
  text "Material" at 11130.23,7830 h60
  text "Thickness" at 11990,7830 h60
  text "Constant" at 12639.84,7830 h60
  text "Board Layer Stack" at 13209.7,7830 h60
  text "1" at 9790.58,7710 h60
  text "Top Overlay" at 10200.49,7710 h60
  text "2" at 9790.58,7590 h60
  text "Top Solder" at 10200.49,7590 h60
  text "Solder Resist" at 11130.23,7590 h60
  text "0.40mil" at 11990,7590 h60
  text "3.5" at 12639.84,7590 h60
  text "3" at 9790.58,7470 h60
  text "Top Layer" at 10200.49,7470 h60
  text "Copper" at 11130.23,7470 h60
  text "1.40mil" at 11990,7470 h60
  text "4" at 9790.58,7350 h60
  text "Dielectric1" at 10200.49,7350 h60
  text "FR-4" at 11130.23,7350 h60
  text "59.20mil" at 11990,7350 h60
  text "4.8" at 12639.84,7350 h60
  text "5" at 9790.58,7230 h60
  text "Bottom Layer" at 10200.49,7230 h60
  text "Copper" at 11130.23,7230 h60
  text "1.40mil" at 11990,7230 h60
  text "6" at 9790.58,7110 h60
  text "Bottom Solder" at 10200.49,7110 h60
  text "Solder Resist" at 11130.23,7110 h60
  text "0.40mil" at 11990,7110 h60
  text "3.5" at 12639.84,7110 h60
  text "7" at 9790.58,6990 h60
  text "Bottom Overlay" at 10200.49,6990 h60
  text ".Layer_Name" at 577,-853.49 h60
Mechanical 13:
  text ".Layer_Name" at 577,-853.49 h60
Mechanical 14:
  text ".Layer_Name" at 577,-853.49 h60
Mechanical 15:
  text ".Layer_Name" at 577,-853.49 h60
Mechanical 16:
  text ".Layer_Name" at 577,-853.49 h60
Drill Drawing:
  text ".Layer_Name" at 577,-853.49 h60

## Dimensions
0,-400 to 1000,-400 on Mechanical 2
0,0 to 4950,0 on Mechanical 2
0,0 to 0,3450 on Mechanical 2
0,-395 to 1000,-395 on Mechanical 2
